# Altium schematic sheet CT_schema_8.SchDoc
size 296 x 239 mm
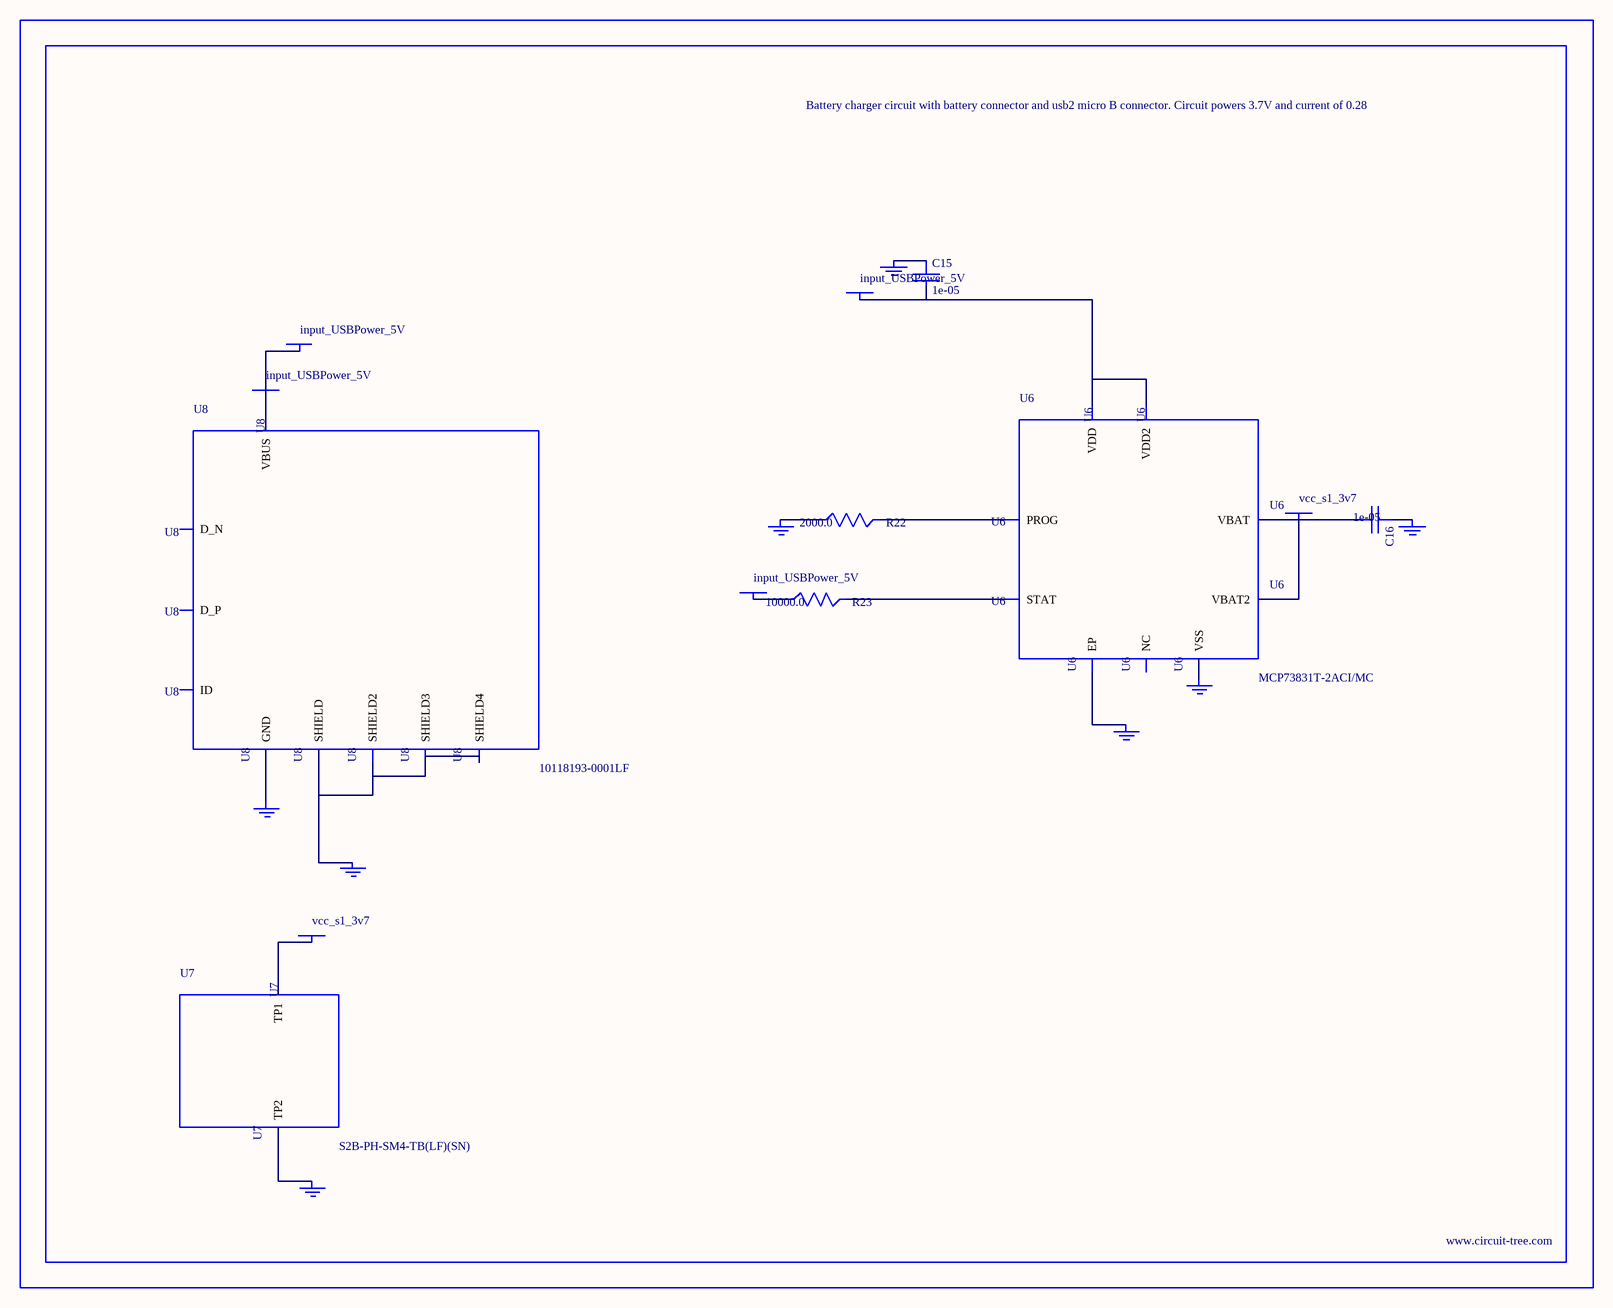
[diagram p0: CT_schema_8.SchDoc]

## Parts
BORDER7  (no value)
C15  1e-05  [C1206]
C16  1e-05  [C1206]
GND_INSTANCE_7_0  (no value)
GND_INSTANCE_7_1  (no value)
GND_INSTANCE_7_2  (no value)
GND_INSTANCE_7_3  (no value)
GND_INSTANCE_7_4  (no value)
GND_INSTANCE_7_5  (no value)
GND_INSTANCE_7_6  (no value)
GND_INSTANCE_7_7  (no value)
POWER_INSTANCE_7_0  input_USBPower_5V
POWER_INSTANCE_7_1  input_USBPower_5V
POWER_INSTANCE_7_2  vcc_s1_3v7
POWER_INSTANCE_7_3  vcc_s1_3v7
POWER_INSTANCE_7_4  input_USBPower_5V
POWER_INSTANCE_7_5  input_USBPower_5V
R22  2000.0  [R0603]
R23  10000.0  [R0603]
U6  MCP73831T-2ACI/MC  [DFN8_2X3MC]
U7  S2B-PH-SM4-TB(LF)(SN)  [JST-2-SMD]
U8  10118193-0001LF  [FCI_10118193-0001LF]

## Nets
NetC15_1: C15.1 GND_INSTANCE_7_0.0(GND)
NetC15_2: C15.2 POWER_INSTANCE_7_0.0(PWR) U6.1(VDD) U6.2(VDD2)
NetC16_1: C16.1 GND_INSTANCE_7_1.0(GND)
NetC16_2: C16.2 POWER_INSTANCE_7_2.0(PWR) U6.3(VBAT) U6.4(VBAT2)
NetGND_INSTANCE_7_2_0: GND_INSTANCE_7_2.0(GND) R22.1
NetGND_INSTANCE_7_3_0: GND_INSTANCE_7_3.0(GND) U6.9(EP)
NetGND_INSTANCE_7_4_0: GND_INSTANCE_7_4.0(GND) U6.6(VSS)
NetGND_INSTANCE_7_5_0: GND_INSTANCE_7_5.0(GND) U7.2(TP2)
NetGND_INSTANCE_7_6_0: GND_INSTANCE_7_6.0(GND) U8.6(SHIELD) U8.7(SHIELD2) U8.8(SHIELD3) U8.9(SHIELD4)
NetGND_INSTANCE_7_7_0: GND_INSTANCE_7_7.0(GND) U8.5(GND)
NetPOWER_INSTANCE_7_1_0: POWER_INSTANCE_7_1.0(PWR) R23.1
NetPOWER_INSTANCE_7_3_0: POWER_INSTANCE_7_3.0(PWR) U7.1(TP1)
NetPOWER_INSTANCE_7_4_0: POWER_INSTANCE_7_4.0(PWR) POWER_INSTANCE_7_5.0(PWR) U8.1(VBUS)
NetR22_2: R22.2 U6.8(PROG)
NetR23_2: R23.2 U6.5(STAT)

Not connected (* = marked no-connect by the designer): U6 7(NC); U8 2(D_N) 3(D_P) 4(ID)

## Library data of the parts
BORDER7 = BORDER_PAGE7
C15 C16 = C1206C106K3RACTU
GND_INSTANCE_7_0-GND_INSTANCE_7_7 = GND
POWER_INSTANCE_7_0-POWER_INSTANCE_7_5 = PWR
R22 = RC0603JR-072KL
R23 = RC0603JR-0710KL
